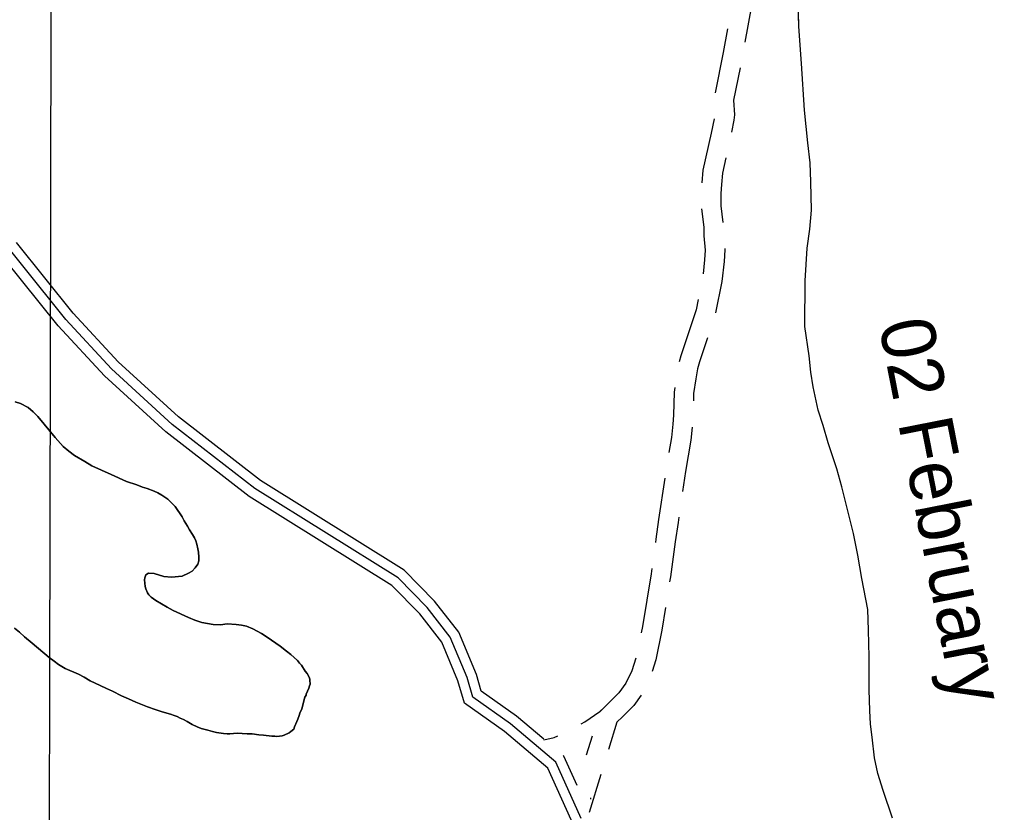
# Model space of a CAD drawing. Extents: x 3192952 to 3230831, y 849296 to 874698.
# Drawn here: x 3207564 to 3209059, y 856825 to 858041 of the extents above; entities that cross this region are included whole.
import ezdxf

# ---------------------------------------------------------------- set-up
doc = ezdxf.new("R2010")
doc.units = 0
for name, color, linetype in [('V-GRID-MAJR', 7, 'Continuous'), ('V-RIVR-IDEN', 7, 'Continuous'), ('V-ROAD-CNTR', 7, 'Continuous'), ('V-SITE-VEGE', 7, 'Continuous'), ('V-TOPO-SHOR', 7, 'Continuous')]:
    doc.layers.add(name, color=color, linetype=linetype)

msp = doc.modelspace()

# ---------------------------------------------------------------- linework, layer by layer
at = {"layer": 'V-GRID-MAJR'}
msp.add_spline([(3207605.4, 854713.5), (3207617.8, 860773), (3207630.1, 866835.5), (3207642.5, 872898.1), (3207642.5, 872901.1)], degree=3, dxfattribs=at)
at = {"layer": 'V-ROAD-CNTR'}
msp.add_line((3208455.2, 856883.5), (3208437.4, 856825.3), dxfattribs=at)
for points in [[(3208693.7, 858104.6), (3208691.9, 858093.3), (3208676.1, 858006.2)], [(3208649.3, 858026.7), (3208642.8, 857990.5), (3208630.4, 857928.5)], [(3208668.6, 857966.9), (3208658.8, 857917.6), (3208659.9, 857895.2), (3208658.9, 857887), (3208655.3, 857868.3)], [(3208628.7, 857888.8), (3208624.5, 857866.9), (3208611.7, 857810.1), (3208610.1, 857790.7)], [(3208646.8, 857829.2), (3208641.5, 857805.6), (3208640, 857788.3), (3208639.1, 857774.2), (3208639.2, 857755.3), (3208642.2, 857730.1)], [(3208609.5, 857750.7), (3208612.9, 857722.7), (3208613.3, 857709.4), (3208615.2, 857687.7), (3208614.3, 857672.7), (3208611.8, 857651.2)], [(3208425.2, 856816.2), (3208386.2, 856902.4), (3208316.6, 856961.4), (3208258.8, 857001.9), (3208250.1, 857032.2), (3208224.3, 857094.2), (3208188.8, 857139.6), (3208144.2, 857184.9), (3207924.8, 857322), (3207797.8, 857420.4), (3207704.7, 857505.4), (3207634.6, 857581.2), (3207502.5, 857745.8)], [(3208367.5, 856937.9), (3208325.8, 856973.2), (3208271.8, 857011.1), (3208264.3, 857037.1), (3208237.4, 857101.8), (3208200, 857149.5), (3208153.6, 857196.7), (3207933.4, 857334.3), (3207807.5, 857431.9), (3207715.3, 857516.1), (3207646, 857591), (3207559, 857699.4)], [(3208645.1, 857690.2), (3208645.3, 857688.1), (3208644.2, 857670.1), (3208640.6, 857639.4), (3208631.1, 857591.4)], [(3208405.6, 856780.8), (3208409.8, 856813.9), (3208373.9, 856893.1), (3208307.4, 856949.5), (3208245.9, 856992.7), (3208235.9, 857027.2), (3208211.3, 857086.5), (3208177.5, 857129.7), (3208134.7, 857173.1), (3207916.2, 857309.7), (3207788.1, 857408.9), (3207694.1, 857494.8), (3207623.2, 857571.4), (3207540, 857675.1)], [(3208604.6, 857611.9), (3208601.5, 857596), (3208577.9, 857525.3), (3208575.3, 857516.3)], [(3208618.9, 857553.3), (3208606.6, 857516.3), (3208603.4, 857505.6), (3208600.6, 857490), (3208597.4, 857467.5), (3208597.1, 857456.3)], [(3208568.4, 857477), (3208567.5, 857470), (3208566.5, 857434.3), (3208565.5, 857420.7), (3208563.5, 857400.3), (3208559.6, 857377.5)], [(3208595.2, 857416.3), (3208593.2, 857396.3), (3208585.1, 857348.1), (3208580.6, 857317.4)], [(3208553.3, 857338), (3208543.8, 857274.3), (3208539.6, 857244.6), (3208538.8, 857239.1)], [(3208574.6, 857277.9), (3208573.5, 857270), (3208569.3, 857240.5), (3208561.9, 857186.7), (3208560.6, 857178.9)], [(3208533.4, 857199.4), (3208532.2, 857191.2), (3208519, 857110.3), (3208517.2, 857100.8)], [(3208554.2, 857139.4), (3208548.5, 857105), (3208539.6, 857059.2), (3208533.9, 857041.6)], [(3208508.9, 857061.7), (3208502.6, 857042.6), (3208493.3, 857023.5), (3208482.6, 857008.8), (3208467, 856993.1), (3208453.9, 856980.3)], [(3208517.2, 857005.4), (3208505.5, 856989.3), (3208488.2, 856971.8), (3208479.8, 856963.7), (3208467, 856921.8)], [(3208424.9, 856961.3), (3208430.5, 856964.5), (3208453.7, 856980), (3208456.2, 856982.5)], [(3208368, 856936.7), (3208383.4, 856940.1), (3208389.4, 856942.9)], [(3208441.9, 856942.2), (3208432.9, 856913)], [(3208418.7, 856866.9), (3208398.4, 856911.6), (3208397.2, 856912.6)], [(3208439.9, 856845.9), (3208439.6, 856847.9)]]:
    msp.add_lwpolyline(points, dxfattribs=at)
at = {"layer": 'V-SITE-VEGE'}
for p, q in [((3208758.9, 858030.4), (3208756.7, 858101.8)), ((3208762.6, 857973.6), (3208758.9, 858030.4)), ((3208767.4, 857902.2), (3208762.6, 857973.6)), ((3208772.4, 857851.9), (3208767.4, 857902.2)), ((3208776.2, 857821.5), (3208772.4, 857851.9)), ((3208777.3, 857792.5), (3208776.2, 857821.5)), ((3208778.4, 857748.8), (3208777.3, 857792.5)), ((3208775.5, 857719.8), (3208778.4, 857748.8)), ((3208771.4, 857690.7), (3208775.5, 857719.8)), ((3208768.5, 857640.5), (3208771.4, 857690.7)), ((3208768, 857570.5), (3208768.5, 857640.5)), ((3208774.4, 857525.5), (3208768, 857570.5)), ((3208776.9, 857500.4), (3208774.4, 857525.5)), ((3208780.7, 857477.9), (3208776.9, 857500.4)), ((3208788.4, 857442.2), (3208780.7, 857477.9)), ((3207557.3, 857454.8), (3207565.5, 857452.6)), ((3207565.5, 857452.6), (3207577.1, 857446.1)), ((3207577.1, 857446.1), (3207584.9, 857439.5)), ((3207584.9, 857439.5), (3207592.1, 857432.2)), ((3208796.2, 857418.4), (3208788.4, 857442.2)), ((3207592.1, 857432.2), (3207618.3, 857400.1)), ((3208803.9, 857391.9), (3208796.2, 857418.4)), ((3207618.3, 857400.1), (3207630.7, 857386.6)), ((3208816.9, 857352.2), (3208803.9, 857391.9)), ((3207630.7, 857386.6), (3207639.3, 857379.2)), ((3207639.3, 857379.2), (3207647.9, 857372.7)), ((3207647.9, 857372.7), (3207663.8, 857363.5)), ((3207663.8, 857363.5), (3207674.6, 857357)), ((3207674.6, 857357), (3207704.3, 857343.4)), ((3207704.3, 857343.4), (3207727.9, 857332.9)), ((3208824.7, 857324.4), (3208816.9, 857352.2)), ((3207727.9, 857332.9), (3207743.9, 857327.6)), ((3207743.9, 857327.6), (3207752.5, 857324.1)), ((3207752.5, 857324.1), (3207759.8, 857321.9)), ((3207759.8, 857321.9), (3207770.1, 857318)), ((3207770.1, 857318), (3207775.7, 857315.4)), ((3207775.7, 857315.4), (3207782.2, 857311.9)), ((3208831.1, 857297.9), (3208824.7, 857324.4)), ((3207782.2, 857311.9), (3207791.2, 857305.8)), ((3207791.2, 857305.8), (3207802.4, 857294.5)), ((3207802.4, 857294.5), (3207813.1, 857278.4)), ((3208842.7, 857252.9), (3208831.1, 857297.9)), ((3207813.1, 857278.4), (3207816.5, 857272.4)), ((3207816.5, 857272.4), (3207821.6, 857264.2)), ((3207821.6, 857264.2), (3207824.6, 857258.5)), ((3207824.6, 857258.5), (3207828.9, 857251.6)), ((3207828.9, 857251.6), (3207831.9, 857246.4)), ((3207831.9, 857246.4), (3207834, 857241.6)), ((3207834, 857241.6), (3207835.7, 857236.9)), ((3208849.1, 857219.8), (3208842.7, 857252.9)), ((3207835.7, 857236.9), (3207837.4, 857229.5)), ((3207837.4, 857229.5), (3207838.2, 857224.3)), ((3207838.2, 857224.3), (3207838.6, 857216.6)), ((3207838.6, 857211.4), (3207837.2, 857206.2)), ((3207838.6, 857216.6), (3207838.6, 857211.4)), ((3208855.5, 857184.1), (3208849.1, 857219.8)), ((3207828.5, 857195.5), (3207822.9, 857192.1)), ((3207832.9, 857200.2), (3207828.5, 857195.5)), ((3207837.2, 857206.2), (3207832.9, 857200.2)), ((3207756, 857185.1), (3207755.5, 857182.1)), ((3207755.5, 857182.1), (3207756.3, 857171.7)), ((3207757.3, 857189.9), (3207756, 857185.1)), ((3207761.6, 857192.4), (3207757.3, 857189.9)), ((3207770.2, 857191.5), (3207761.6, 857192.4)), ((3207784.9, 857187.1), (3207770.2, 857191.5)), ((3207797, 857186.2), (3207784.9, 857187.1)), ((3207813.4, 857187.8), (3207797, 857186.2)), ((3207822.9, 857192.1), (3207813.4, 857187.8)), ((3208864.5, 857136.5), (3208855.5, 857184.1)), ((3207756.3, 857171.7), (3207757.6, 857168.3)), ((3207757.6, 857168.3), (3207760.1, 857162.2)), ((3207760.1, 857162.2), (3207762.3, 857159.2)), ((3207762.3, 857159.2), (3207765.7, 857155.7)), ((3207765.7, 857155.7), (3207772.6, 857150.5)), ((3207772.6, 857150.5), (3207790.2, 857140)), ((3207790.2, 857140), (3207799.3, 857135.2)), ((3207799.3, 857135.2), (3207822.9, 857124.3)), ((3208865.6, 857104.8), (3208864.5, 857136.5)), ((3207822.9, 857124.3), (3207832.8, 857120.4)), ((3207832.8, 857120.4), (3207843.2, 857116.8)), ((3207563.8, 857101.7), (3207556.1, 857107.8)), ((3207843.2, 857116.8), (3207860.8, 857113.7)), ((3207860.8, 857113.7), (3207872.1, 857113.2)), ((3207872.1, 857113.2), (3207882.4, 857114.4)), ((3207882.4, 857114.4), (3207896.2, 857113.5)), ((3207896.2, 857113.5), (3207904.4, 857112.6)), ((3207904.4, 857112.6), (3207911.8, 857110.8)), ((3207911.8, 857110.8), (3207921.7, 857106.9)), ((3207921.7, 857106.9), (3207935, 857099.9)), ((3208866.7, 857063.8), (3208865.6, 857104.8)), ((3207571.5, 857094.7), (3207563.8, 857101.7)), ((3207583.1, 857084.7), (3207571.5, 857094.7)), ((3207935, 857099.9), (3207944.9, 857093.3)), ((3207944.9, 857093.3), (3207950, 857089.4)), ((3207950, 857089.4), (3207963.4, 857080.3)), ((3207609.3, 857063), (3207583.1, 857084.7)), ((3207963.4, 857080.3), (3207973.3, 857072.9)), ((3207617.1, 857057.4), (3207609.3, 857063)), ((3207973.3, 857072.9), (3207979.7, 857067.7)), ((3207979.7, 857067.7), (3207990, 857058.1)), ((3208866.4, 857013.6), (3208866.7, 857063.8)), ((3207623.5, 857052.1), (3207617.1, 857057.4)), ((3207633.8, 857046), (3207623.5, 857052.1)), ((3207654.1, 857037.3), (3207633.8, 857046)), ((3207990, 857058.1), (3207993, 857054.2)), ((3207993, 857054.2), (3207996, 857051.2)), ((3207996, 857051.2), (3208002, 857042.1)), ((3207663.1, 857032.9), (3207654.1, 857037.3)), ((3207672.1, 857027.2), (3207663.1, 857032.9)), ((3208002, 857042.1), (3208005, 857038.2)), ((3208005, 857038.2), (3208008, 857033)), ((3208008, 857033), (3208009.2, 857029.9)), ((3208009.2, 857029.9), (3208009.2, 857028.3)), ((3207687.6, 857020.2), (3207672.1, 857027.2)), ((3207697.1, 857015.4), (3207687.6, 857020.2)), ((3207706.6, 857011.1), (3207697.1, 857015.4)), ((3208007.3, 857016.1), (3208003.2, 857006.5)), ((3208008.5, 857019.3), (3208007.3, 857016.1)), ((3208009.3, 857022.3), (3208008.5, 857019.3)), ((3208009.2, 857028.3), (3208009.3, 857022.3)), ((3207720.3, 857004.1), (3207706.6, 857011.1)), ((3207731.1, 856999.7), (3207720.3, 857004.1)), ((3207742.3, 856994.4), (3207731.1, 856999.7)), ((3208001.3, 857001.9), (3207996.9, 856984.3)), ((3208003.1, 857005.4), (3208001.3, 857001.9)), ((3208003.2, 857006.5), (3208003.1, 857005.4)), ((3208867.5, 856981.9), (3208866.4, 857013.6)), ((3207759.9, 856987.4), (3207742.3, 856994.4)), ((3207771.6, 856983), (3207759.9, 856987.4)), ((3207782.3, 856979.9), (3207771.6, 856983)), ((3207795.3, 856976), (3207782.3, 856979.9)), ((3207800.9, 856974.2), (3207795.3, 856976)), ((3207805.6, 856972.5), (3207800.9, 856974.2)), ((3207810.3, 856969.8), (3207805.6, 856972.5)), ((3207815.5, 856967.7), (3207810.3, 856969.8)), ((3207992.5, 856973.9), (3207990.7, 856968.3)), ((3207993.8, 856977.4), (3207992.5, 856973.9)), ((3207996.9, 856984.3), (3207993.8, 856977.4)), ((3208868.7, 856960.7), (3208867.5, 856981.9)), ((3207820.7, 856964.6), (3207815.5, 856967.7)), ((3207828.8, 856960.2), (3207820.7, 856964.6)), ((3207836.1, 856956.7), (3207828.8, 856960.2)), ((3207842.6, 856954.1), (3207836.1, 856956.7)), ((3207985.5, 856956.7), (3207984.2, 856953.3)), ((3207989, 856964.9), (3207985.5, 856956.7)), ((3207990.7, 856968.3), (3207989, 856964.9)), ((3208871.2, 856940.9), (3208868.7, 856960.7)), ((3207852.5, 856951.5), (3207842.6, 856954.1)), ((3207859.8, 856949.7), (3207852.5, 856951.5)), ((3207865.9, 856947.9), (3207859.8, 856949.7)), ((3207876.7, 856946.6), (3207865.9, 856947.9)), ((3207882.3, 856946.1), (3207876.7, 856946.6)), ((3207886.2, 856946.1), (3207882.3, 856946.1)), ((3207897.8, 856946.9), (3207886.2, 856946.1)), ((3207912.9, 856945.9), (3207897.8, 856946.9)), ((3207920.7, 856945.9), (3207912.9, 856945.9)), ((3207931, 856944.5), (3207920.7, 856945.9)), ((3207937.9, 856944), (3207931, 856944.5)), ((3207950.9, 856942.2), (3207937.9, 856944)), ((3207955.2, 856942.2), (3207950.9, 856942.2)), ((3207958.6, 856941.8), (3207955.2, 856942.2)), ((3207966.4, 856943), (3207958.6, 856941.8)), ((3207969.4, 856943.8), (3207966.4, 856943)), ((3207977.2, 856947.7), (3207969.4, 856943.8)), ((3207979.8, 856949.4), (3207977.2, 856947.7)), ((3207984.2, 856953.3), (3207979.8, 856949.4)), ((3208875, 856909.1), (3208871.2, 856940.9)), ((3208880.1, 856885.3), (3208875, 856909.1)), ((3208887.9, 856858.8), (3208880.1, 856885.3)), ((3208902.2, 856816.5), (3208887.9, 856858.8))]:
    msp.add_line(p, q, dxfattribs=at)
at = {"layer": 'V-TOPO-SHOR'}
for points in [[(3208902.2, 856816.5), (3208887.9, 856858.8), (3208880.1, 856885.3), (3208875, 856909.1), (3208871.2, 856940.9), (3208868.7, 856960.7), (3208867.5, 856981.9), (3208866.4, 857013.6), (3208866.7, 857063.8), (3208865.6, 857104.8), (3208864.5, 857136.5), (3208855.5, 857184.1), (3208849.1, 857219.8), (3208842.7, 857252.9), (3208831.1, 857297.9), (3208824.7, 857324.4), (3208816.9, 857352.2), (3208803.9, 857391.9), (3208796.2, 857418.4), (3208788.4, 857442.2), (3208780.7, 857477.9), (3208776.9, 857500.4), (3208774.4, 857525.5), (3208768, 857570.5), (3208768.5, 857640.5), (3208771.4, 857690.7), (3208775.5, 857719.8), (3208778.4, 857748.8), (3208777.3, 857792.5), (3208776.2, 857821.5), (3208772.4, 857851.9), (3208767.4, 857902.2), (3208762.6, 857973.6), (3208758.9, 858030.4), (3208756.7, 858101.8)], [(3208009.2, 857028.3), (3208009.2, 857029.9), (3208008, 857033), (3208005, 857038.2), (3208002, 857042.1), (3207996, 857051.2), (3207993, 857054.2), (3207990, 857058.1), (3207979.7, 857067.7), (3207973.3, 857072.9), (3207963.4, 857080.3), (3207950, 857089.4), (3207944.9, 857093.3), (3207935, 857099.9), (3207921.7, 857106.9), (3207911.8, 857110.8), (3207904.4, 857112.6), (3207896.2, 857113.5), (3207882.4, 857114.4), (3207872.1, 857113.2), (3207860.8, 857113.7), (3207843.2, 857116.8), (3207832.8, 857120.4), (3207822.9, 857124.3), (3207799.3, 857135.2), (3207790.2, 857140), (3207772.6, 857150.5), (3207765.7, 857155.7), (3207762.3, 857159.2), (3207760.1, 857162.2), (3207757.6, 857168.3), (3207756.3, 857171.7), (3207755.5, 857182.1), (3207756, 857185.1), (3207757.3, 857189.9), (3207761.6, 857192.4), (3207770.2, 857191.5), (3207784.9, 857187.1), (3207797, 857186.2), (3207813.4, 857187.8), (3207822.9, 857192.1), (3207828.5, 857195.5), (3207832.9, 857200.2), (3207837.2, 857206.2), (3207838.6, 857211.4), (3207838.6, 857216.6), (3207838.2, 857224.3), (3207837.4, 857229.5), (3207835.7, 857236.9), (3207834, 857241.6), (3207831.9, 857246.4), (3207828.9, 857251.6), (3207824.6, 857258.5), (3207821.6, 857264.2), (3207816.5, 857272.4), (3207813.1, 857278.4), (3207802.4, 857294.5), (3207791.2, 857305.8), (3207782.2, 857311.9), (3207775.7, 857315.4), (3207770.1, 857318), (3207759.8, 857321.9), (3207752.5, 857324.1), (3207743.9, 857327.6), (3207727.9, 857332.9), (3207704.3, 857343.4), (3207674.6, 857357), (3207663.8, 857363.5), (3207647.9, 857372.7), (3207639.3, 857379.2), (3207630.7, 857386.6), (3207618.3, 857400.1), (3207592.1, 857432.2), (3207584.9, 857439.5), (3207577.1, 857446.1), (3207565.5, 857452.6), (3207557.3, 857454.8)], [(3207556.1, 857107.8), (3207563.8, 857101.7), (3207571.5, 857094.7), (3207583.1, 857084.7), (3207609.3, 857063), (3207617.1, 857057.4), (3207623.5, 857052.1), (3207633.8, 857046), (3207654.1, 857037.3), (3207663.1, 857032.9), (3207672.1, 857027.2), (3207687.6, 857020.2), (3207697.1, 857015.4), (3207706.6, 857011.1), (3207720.3, 857004.1), (3207731.1, 856999.7), (3207742.3, 856994.4), (3207759.9, 856987.4), (3207771.6, 856983), (3207782.3, 856979.9), (3207795.3, 856976), (3207800.9, 856974.2), (3207805.6, 856972.5), (3207810.3, 856969.8), (3207815.5, 856967.7), (3207820.7, 856964.6), (3207828.8, 856960.2), (3207836.1, 856956.7), (3207842.6, 856954.1), (3207852.5, 856951.5), (3207859.8, 856949.7), (3207865.9, 856947.9), (3207876.7, 856946.6), (3207882.3, 856946.1), (3207886.2, 856946.1), (3207897.8, 856946.9), (3207912.9, 856945.9), (3207920.7, 856945.9), (3207931, 856944.5), (3207937.9, 856944), (3207950.9, 856942.2), (3207955.2, 856942.2), (3207958.6, 856941.8), (3207966.4, 856943), (3207969.4, 856943.8), (3207977.2, 856947.7), (3207979.8, 856949.4), (3207984.2, 856953.3), (3207985.5, 856956.7), (3207989, 856964.9), (3207990.7, 856968.3), (3207992.5, 856973.9)], [(3208003.2, 857006.5), (3208007.3, 857016.1), (3208008.5, 857019.3), (3208009.3, 857022.3), (3208009.2, 857028.3)], [(3207992.5, 856973.9), (3207993.8, 856977.4), (3207996.9, 856984.3), (3208001.3, 857001.9), (3208003.1, 857005.4), (3208003.2, 857006.5)]]:
    msp.add_lwpolyline(points, dxfattribs=at)

# ---------------------------------------------------------------- texts
at = {"layer": 'V-RIVR-IDEN'}
msp.add_text('02 February', height=83, rotation=281.111, dxfattribs=at).set_placement((3208880.9, 857574.7))

doc.saveas('drawing.dxf')
